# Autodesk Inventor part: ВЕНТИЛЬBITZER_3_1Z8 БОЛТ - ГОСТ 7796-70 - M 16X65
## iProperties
Created: 2011-02
Part Number: ВЕНТИЛЬBITZER_3_1Z8 БОЛТ - ГОСТ 7796-70 - M 16X65
Document SubType Name: Modeling
Designer: Чернышев Юрий
Mass: 16.7089 g
Surface Area: 47.6443 cm^2
Volume: 16.7089 cm^3
Density: 1 g/cm^3
Author: Чернышев Юрий
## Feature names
1. Base1
